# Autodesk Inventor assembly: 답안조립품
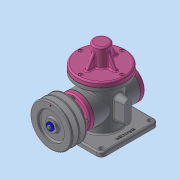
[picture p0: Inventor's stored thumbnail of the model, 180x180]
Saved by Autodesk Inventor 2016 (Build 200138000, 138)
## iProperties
Created: 2020-02
Part Number: 답안조립품
Material: 일반
Document SubType Name: Assembly
Designer: Administrator
Author: Administrator
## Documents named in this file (21)
- C:\Users\Administrator\Desktop\600206V1002\답안조립품.iam
- C:\Users\Administrator\Desktop\600206V1002\본체.ipt
- C:\Users\Administrator\Desktop\600206V1002\링크.ipt
- C:\Users\Administrator\Desktop\600206V1002\클레비스 핀 6 x 22.ipt
- 클레비스 핀 6 x 22.ipt
- C:\Users\Administrator\Desktop\600206V1002\E-링.ipt
- C:\Users\Administrator\Desktop\600206V1002\슬라이더.ipt
- C:\Users\Administrator\Desktop\600206V1002\가변스프링.ipt
- C:\Users\Administrator\Desktop\600206V1002\덮개.ipt
- C:\Users\Administrator\Desktop\600206V1002\개스킷 B.ipt
- C:\Users\Administrator\Desktop\600206V1002\육각 소켓 머리 볼트 M4 x 10.ipt
- C:\Users\Administrator\Desktop\600206V1002\베어링 17 x 40 x 12.ipt
- C:\Users\Administrator\Desktop\600206V1002\뒤커버.ipt
- C:\Users\Administrator\Desktop\600206V1002\개스킷 A.ipt
- C:\Users\Administrator\Desktop\600206V1002\V-벨트풀리.ipt
- C:\Users\Administrator\Desktop\600206V1002\와셔 4x16.ipt
- C:\Users\Administrator\Desktop\600206V1002\볼트 M4 x 10.ipt
- C:\Users\Administrator\Desktop\600206V1002\앞커버.ipt
- C:\Users\Administrator\Desktop\600206V1002\오일 실 17 30 8.ipt
- C:\Users\Administrator\Desktop\600206V1002\편심축.ipt
- C:\Users\Administrator\Desktop\600206V1002\키 4 x 4 x 25.ipt
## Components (6 placed, 5 different names)
1. E-링:1
2. 개스킷 B:1
3. 개스킷 A:1
4. V-벨트풀리:1 — 각도:2
5. 개스킷 A:2
6. 가변스프링:1
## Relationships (1: Angle 1)
- 각도:2 [Angle]: V-벨트풀리:1
